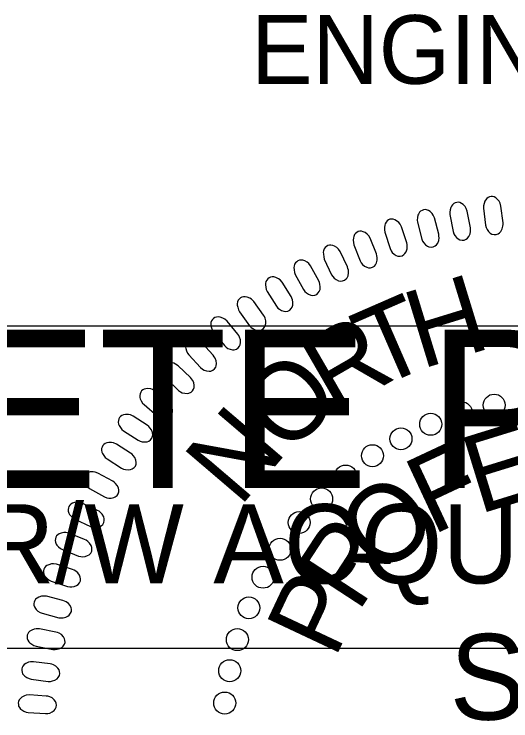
# Model space of a CAD drawing. Extents: x 505602 to 507286, y 483109 to 484209.
# Drawn here: x 507178.9 to 507215, y 484097.2 to 484148.7 of the extents above; entities that cross this region are included whole.
import ezdxf

# ---------------------------------------------------------------- set-up
doc = ezdxf.new("R2010")
doc.units = 0
for name, color, linetype in [('Sheet PE Seal Cell', 7, 'Continuous'), ('Sheet Profile CELL', 7, 'Continuous'), ('Sheet Sticker Incomplete CELL', 7, 'Continuous')]:
    doc.layers.add(name, color=color, linetype=linetype)

msp = doc.modelspace()

# ---------------------------------------------------------------- linework, layer by layer
at = {"layer": 'Sheet PE Seal Cell'}
for points in [[(507214.482, 484133.512), (507214.328, 484134.729), (507214.264, 484134.942), (507214.194, 484135.074), (507214.062, 484135.228), (507213.952, 484135.325), (507213.831, 484135.39), (507213.722, 484135.417), (507213.608, 484135.423), (507213.499, 484135.388), (507213.384, 484135.344), (507213.288, 484135.272), (507213.196, 484135.16), (507213.147, 484135.073), (507213.099, 484134.916), (507213.062, 484134.731), (507213.06, 484134.569), (507213.21, 484133.322), (507213.253, 484133.156), (507213.315, 484133.023), (507213.424, 484132.876), (507213.553, 484132.752), (507213.659, 484132.685), (507213.822, 484132.645), (507213.973, 484132.644), (507214.116, 484132.702), (507214.214, 484132.765), (507214.328, 484132.88), (507214.425, 484133.062), (507214.469, 484133.249), (507214.483, 484133.381)], [(507212.1, 484133.144), (507211.871, 484134.348), (507211.793, 484134.557), (507211.716, 484134.685), (507211.574, 484134.831), (507211.458, 484134.92), (507211.333, 484134.978), (507211.223, 484134.997), (507211.109, 484134.996), (507211.002, 484134.955), (507210.891, 484134.903), (507210.799, 484134.825), (507210.714, 484134.707), (507210.671, 484134.618), (507210.633, 484134.458), (507210.608, 484134.271), (507210.615, 484134.11), (507210.843, 484132.874), (507210.897, 484132.712), (507210.967, 484132.583), (507211.085, 484132.443), (507211.221, 484132.327), (507211.332, 484132.267), (507211.497, 484132.237), (507211.647, 484132.246), (507211.787, 484132.313), (507211.881, 484132.381), (507211.987, 484132.503), (507212.073, 484132.692), (507212.105, 484132.881), (507212.11, 484133.014)], [(507209.795, 484132.672), (507209.491, 484133.86), (507209.4, 484134.063), (507209.314, 484134.186), (507209.164, 484134.322), (507209.042, 484134.404), (507208.914, 484134.453), (507208.802, 484134.467), (507208.689, 484134.458), (507208.585, 484134.411), (507208.477, 484134.352), (507208.39, 484134.268), (507208.314, 484134.145), (507208.276, 484134.053), (507208.247, 484133.891), (507208.234, 484133.703), (507208.252, 484133.543), (507208.557, 484132.324), (507208.621, 484132.165), (507208.699, 484132.041), (507208.826, 484131.909), (507208.969, 484131.801), (507209.083, 484131.749), (507209.25, 484131.729), (507209.4, 484131.747), (507209.535, 484131.822), (507209.624, 484131.897), (507209.722, 484132.025), (507209.795, 484132.219), (507209.816, 484132.41), (507209.813, 484132.542)], [(507207.461, 484132.051), (507207.083, 484133.218), (507206.98, 484133.415), (507206.887, 484133.532), (507206.728, 484133.659), (507206.602, 484133.733), (507206.47, 484133.774), (507206.358, 484133.78), (507206.246, 484133.764), (507206.145, 484133.711), (507206.041, 484133.645), (507205.96, 484133.556), (507205.891, 484133.429), (507205.859, 484133.334), (507205.84, 484133.171), (507205.839, 484132.982), (507205.867, 484132.823), (507206.248, 484131.626), (507206.322, 484131.472), (507206.407, 484131.353), (507206.542, 484131.229), (507206.692, 484131.13), (507206.809, 484131.085), (507206.977, 484131.076), (507207.125, 484131.103), (507207.255, 484131.187), (507207.339, 484131.267), (507207.429, 484131.401), (507207.49, 484131.599), (507207.499, 484131.791), (507207.487, 484131.924)], [(507205.261, 484131.235), (507204.809, 484132.376), (507204.694, 484132.566), (507204.594, 484132.677), (507204.427, 484132.793), (507204.297, 484132.859), (507204.163, 484132.892), (507204.051, 484132.891), (507203.94, 484132.868), (507203.843, 484132.808), (507203.742, 484132.736), (507203.667, 484132.642), (507203.606, 484132.511), (507203.58, 484132.415), (507203.572, 484132.251), (507203.583, 484132.062), (507203.621, 484131.906), (507204.076, 484130.734), (507204.159, 484130.585), (507204.253, 484130.472), (507204.395, 484130.356), (507204.55, 484130.267), (507204.67, 484130.229), (507204.838, 484130.231), (507204.984, 484130.268), (507205.108, 484130.36), (507205.187, 484130.445), (507205.269, 484130.584), (507205.318, 484130.785), (507205.314, 484130.978), (507205.295, 484131.109)], [(507203.143, 484130.302), (507202.621, 484131.412), (507202.494, 484131.594), (507202.387, 484131.699), (507202.214, 484131.805), (507202.079, 484131.862), (507201.944, 484131.887), (507201.832, 484131.879), (507201.722, 484131.849), (507201.629, 484131.783), (507201.534, 484131.705), (507201.464, 484131.607), (507201.412, 484131.472), (507201.392, 484131.374), (507201.395, 484131.21), (507201.417, 484131.022), (507201.464, 484130.868), (507201.993, 484129.729), (507202.085, 484129.584), (507202.185, 484129.477), (507202.334, 484129.371), (507202.495, 484129.292), (507202.617, 484129.261), (507202.784, 484129.274), (507202.928, 484129.319), (507203.046, 484129.419), (507203.12, 484129.509), (507203.192, 484129.653), (507203.229, 484129.857), (507203.213, 484130.048), (507203.185, 484130.179)], [(507201.06, 484129.288), (507200.469, 484130.363), (507200.331, 484130.538), (507200.218, 484130.635), (507200.038, 484130.73), (507199.9, 484130.779), (507199.764, 484130.795), (507199.653, 484130.779), (507199.545, 484130.743), (507199.456, 484130.672), (507199.366, 484130.588), (507199.303, 484130.485), (507199.259, 484130.347), (507199.245, 484130.248), (507199.258, 484130.085), (507199.292, 484129.898), (507199.349, 484129.748), (507199.948, 484128.643), (507200.049, 484128.505), (507200.156, 484128.405), (507200.311, 484128.308), (507200.477, 484128.239), (507200.6, 484128.216), (507200.767, 484128.239), (507200.907, 484128.294), (507201.019, 484128.401), (507201.087, 484128.495), (507201.15, 484128.643), (507201.173, 484128.85), (507201.146, 484129.039), (507201.109, 484129.167)], [(507199.043, 484128.146), (507198.386, 484129.182), (507198.237, 484129.348), (507198.118, 484129.437), (507197.933, 484129.521), (507197.792, 484129.561), (507197.655, 484129.568), (507197.544, 484129.546), (507197.439, 484129.503), (507197.355, 484129.426), (507197.27, 484129.337), (507197.214, 484129.23), (507197.179, 484129.09), (507197.171, 484128.99), (507197.194, 484128.828), (507197.24, 484128.644), (507197.306, 484128.497), (507197.973, 484127.432), (507198.083, 484127.301), (507198.196, 484127.207), (507198.357, 484127.121), (507198.526, 484127.063), (507198.651, 484127.047), (507198.816, 484127.081), (507198.952, 484127.144), (507199.058, 484127.258), (507199.119, 484127.356), (507199.173, 484127.508), (507199.183, 484127.716), (507199.144, 484127.903), (507199.1, 484128.028)], [(507197.042, 484126.791), (507196.321, 484127.784), (507196.162, 484127.94), (507196.038, 484128.022), (507195.847, 484128.094), (507195.704, 484128.125), (507195.567, 484128.124), (507195.458, 484128.095), (507195.356, 484128.045), (507195.277, 484127.963), (507195.198, 484127.869), (507195.149, 484127.759), (507195.122, 484127.616), (507195.121, 484127.517), (507195.155, 484127.356), (507195.211, 484127.175), (507195.287, 484127.033), (507196.019, 484126.012), (507196.137, 484125.888), (507196.255, 484125.801), (507196.421, 484125.724), (507196.594, 484125.678), (507196.72, 484125.67), (507196.882, 484125.714), (507197.015, 484125.786), (507197.112, 484125.906), (507197.167, 484126.007), (507197.212, 484126.163), (507197.209, 484126.371), (507197.158, 484126.555), (507197.106, 484126.678)], [(507195.162, 484125.402), (507194.38, 484126.348), (507194.212, 484126.493), (507194.082, 484126.568), (507193.888, 484126.627), (507193.743, 484126.65), (507193.606, 484126.64), (507193.5, 484126.603), (507193.401, 484126.547), (507193.327, 484126.46), (507193.254, 484126.361), (507193.211, 484126.249), (507193.194, 484126.104), (507193.199, 484126.005), (507193.242, 484125.847), (507193.31, 484125.67), (507193.395, 484125.533), (507194.189, 484124.56), (507194.315, 484124.444), (507194.439, 484124.365), (507194.609, 484124.299), (507194.785, 484124.263), (507194.911, 484124.263), (507195.07, 484124.317), (507195.198, 484124.397), (507195.287, 484124.523), (507195.336, 484124.628), (507195.371, 484124.786), (507195.354, 484124.992), (507195.292, 484125.174), (507195.232, 484125.293)], [(507193.374, 484123.863), (507192.535, 484124.758), (507192.357, 484124.893), (507192.223, 484124.959), (507192.025, 484125.006), (507191.88, 484125.019), (507191.744, 484125.001), (507191.64, 484124.958), (507191.544, 484124.896), (507191.476, 484124.804), (507191.409, 484124.7), (507191.374, 484124.586), (507191.366, 484124.441), (507191.377, 484124.342), (507191.43, 484124.187), (507191.51, 484124.015), (507191.602, 484123.884), (507192.457, 484122.962), (507192.589, 484122.854), (507192.717, 484122.783), (507192.892, 484122.728), (507193.07, 484122.702), (507193.195, 484122.71), (507193.35, 484122.774), (507193.473, 484122.863), (507193.554, 484122.994), (507193.597, 484123.102), (507193.622, 484123.261), (507193.593, 484123.466), (507193.518, 484123.644), (507193.452, 484123.759)], [(507191.712, 484122.254), (507190.818, 484123.094), (507190.632, 484123.217), (507190.495, 484123.275), (507190.294, 484123.309), (507190.148, 484123.314), (507190.013, 484123.286), (507189.912, 484123.237), (507189.821, 484123.169), (507189.759, 484123.074), (507189.699, 484122.966), (507189.67, 484122.849), (507189.671, 484122.705), (507189.689, 484122.606), (507189.751, 484122.454), (507189.841, 484122.288), (507189.942, 484122.162), (507190.853, 484121.297), (507190.992, 484121.197), (507191.124, 484121.134), (507191.302, 484121.09), (507191.48, 484121.076), (507191.605, 484121.092), (507191.757, 484121.166), (507191.873, 484121.261), (507191.946, 484121.397), (507191.982, 484121.508), (507191.996, 484121.669), (507191.955, 484121.872), (507191.87, 484122.044), (507191.796, 484122.154)], [(507190.098, 484120.467), (507189.154, 484121.25), (507188.96, 484121.36), (507188.82, 484121.409), (507188.617, 484121.431), (507188.471, 484121.426), (507188.339, 484121.391), (507188.241, 484121.336), (507188.154, 484121.262), (507188.098, 484121.163), (507188.045, 484121.051), (507188.024, 484120.933), (507188.034, 484120.789), (507188.057, 484120.692), (507188.13, 484120.545), (507188.23, 484120.383), (507188.338, 484120.265), (507189.301, 484119.458), (507189.446, 484119.367), (507189.583, 484119.313), (507189.763, 484119.28), (507189.941, 484119.277), (507190.065, 484119.302), (507190.211, 484119.384), (507190.322, 484119.486), (507190.387, 484119.627), (507190.415, 484119.739), (507190.419, 484119.901), (507190.365, 484120.101), (507190.27, 484120.267), (507190.188, 484120.373)], [(507188.574, 484118.765), (507187.544, 484119.431), (507187.339, 484119.518), (507187.193, 484119.55), (507186.99, 484119.548), (507186.845, 484119.526), (507186.718, 484119.475), (507186.628, 484119.409), (507186.55, 484119.325), (507186.505, 484119.221), (507186.466, 484119.104), (507186.459, 484118.984), (507186.486, 484118.842), (507186.52, 484118.748), (507186.61, 484118.61), (507186.728, 484118.462), (507186.85, 484118.357), (507187.901, 484117.669), (507188.056, 484117.596), (507188.197, 484117.558), (507188.38, 484117.546), (507188.558, 484117.565), (507188.678, 484117.604), (507188.813, 484117.703), (507188.911, 484117.817), (507188.959, 484117.965), (507188.974, 484118.079), (507188.959, 484118.24), (507188.882, 484118.432), (507188.767, 484118.587), (507188.674, 484118.682)], [(507187.359, 484116.742), (507186.324, 484117.4), (507186.119, 484117.486), (507185.973, 484117.517), (507185.769, 484117.513), (507185.625, 484117.49), (507185.497, 484117.438), (507185.408, 484117.371), (507185.33, 484117.287), (507185.287, 484117.181), (507185.249, 484117.065), (507185.243, 484116.944), (507185.271, 484116.802), (507185.306, 484116.709), (507185.397, 484116.572), (507185.516, 484116.425), (507185.639, 484116.321), (507186.696, 484115.641), (507186.851, 484115.569), (507186.993, 484115.532), (507187.175, 484115.522), (507187.353, 484115.542), (507187.473, 484115.581), (507187.607, 484115.682), (507187.704, 484115.797), (507187.751, 484115.944), (507187.765, 484116.06), (507187.749, 484116.221), (507187.67, 484116.412), (507187.554, 484116.565), (507187.461, 484116.66)], [(507186.056, 484114.693), (507184.981, 484115.285), (507184.771, 484115.357), (507184.623, 484115.379), (507184.421, 484115.363), (507184.277, 484115.33), (507184.154, 484115.271), (507184.069, 484115.198), (507183.997, 484115.11), (507183.961, 484115.001), (507183.929, 484114.882), (507183.931, 484114.762), (507183.968, 484114.622), (507184.009, 484114.531), (507184.107, 484114.4), (507184.236, 484114.261), (507184.365, 484114.164), (507185.462, 484113.552), (507185.621, 484113.49), (507185.765, 484113.463), (507185.949, 484113.464), (507186.125, 484113.495), (507186.242, 484113.542), (507186.37, 484113.65), (507186.459, 484113.772), (507186.496, 484113.922), (507186.503, 484114.037), (507186.477, 484114.197), (507186.386, 484114.383), (507186.262, 484114.529), (507186.162, 484114.618)], [(507184.947, 484112.569), (507183.837, 484113.092), (507183.623, 484113.152), (507183.474, 484113.164), (507183.273, 484113.135), (507183.132, 484113.094), (507183.013, 484113.026), (507182.932, 484112.948), (507182.866, 484112.855), (507182.836, 484112.745), (507182.813, 484112.624), (507182.822, 484112.505), (507182.868, 484112.367), (507182.914, 484112.279), (507183.021, 484112.155), (507183.158, 484112.024), (507183.292, 484111.935), (507184.427, 484111.393), (507184.589, 484111.342), (507184.735, 484111.323), (507184.917, 484111.336), (507185.091, 484111.378), (507185.205, 484111.431), (507185.326, 484111.548), (507185.408, 484111.675), (507185.435, 484111.827), (507185.435, 484111.943), (507185.399, 484112.101), (507185.297, 484112.281), (507185.163, 484112.418), (507185.058, 484112.501)], [(507184.008, 484110.451), (507182.868, 484110.902), (507182.65, 484110.948), (507182.501, 484110.952), (507182.302, 484110.91), (507182.164, 484110.86), (507182.049, 484110.785), (507181.973, 484110.702), (507181.913, 484110.605), (507181.89, 484110.494), (507181.874, 484110.371), (507181.891, 484110.252), (507181.945, 484110.118), (507181.997, 484110.033), (507182.112, 484109.915), (507182.257, 484109.794), (507182.396, 484109.714), (507183.562, 484109.244), (507183.727, 484109.203), (507183.874, 484109.193), (507184.055, 484109.217), (507184.226, 484109.27), (507184.337, 484109.331), (507184.451, 484109.455), (507184.524, 484109.586), (507184.542, 484109.74), (507184.534, 484109.856), (507184.488, 484110.011), (507184.374, 484110.184), (507184.232, 484110.313), (507184.122, 484110.389)], [(507183.132, 484108.261), (507181.965, 484108.64), (507181.745, 484108.672), (507181.596, 484108.667), (507181.4, 484108.613), (507181.265, 484108.554), (507181.155, 484108.472), (507181.085, 484108.385), (507181.032, 484108.284), (507181.016, 484108.171), (507181.007, 484108.048), (507181.032, 484107.931), (507181.094, 484107.8), (507181.152, 484107.718), (507181.273, 484107.608), (507181.425, 484107.496), (507181.57, 484107.425), (507182.763, 484107.029), (507182.931, 484106.998), (507183.078, 484106.998), (507183.257, 484107.034), (507183.424, 484107.097), (507183.531, 484107.165), (507183.636, 484107.295), (507183.701, 484107.431), (507183.709, 484107.586), (507183.694, 484107.701), (507183.639, 484107.853), (507183.515, 484108.019), (507183.364, 484108.138), (507183.25, 484108.207)], [(507182.428, 484106.006), (507181.239, 484106.311), (507181.018, 484106.329), (507180.869, 484106.314), (507180.677, 484106.247), (507180.547, 484106.181), (507180.441, 484106.092), (507180.377, 484106), (507180.329, 484105.896), (507180.321, 484105.784), (507180.32, 484105.66), (507180.352, 484105.543), (507180.423, 484105.418), (507180.485, 484105.34), (507180.613, 484105.237), (507180.772, 484105.135), (507180.921, 484105.073), (507182.136, 484104.753), (507182.306, 484104.732), (507182.452, 484104.741), (507182.629, 484104.789), (507182.792, 484104.862), (507182.894, 484104.936), (507182.991, 484105.074), (507183.047, 484105.213), (507183.046, 484105.368), (507183.024, 484105.482), (507182.959, 484105.63), (507182.825, 484105.788), (507182.667, 484105.898), (507182.549, 484105.959)], [(507181.916, 484103.71), (507180.712, 484103.94), (507180.489, 484103.945), (507180.342, 484103.92), (507180.154, 484103.841), (507180.028, 484103.767), (507179.929, 484103.671), (507179.87, 484103.576), (507179.829, 484103.47), (507179.828, 484103.356), (507179.835, 484103.233), (507179.874, 484103.119), (507179.952, 484102.997), (507180.019, 484102.924), (507180.154, 484102.829), (507180.319, 484102.737), (507180.471, 484102.685), (507181.705, 484102.441), (507181.875, 484102.432), (507182.021, 484102.45), (507182.194, 484102.508), (507182.352, 484102.592), (507182.449, 484102.672), (507182.537, 484102.815), (507182.585, 484102.958), (507182.574, 484103.113), (507182.544, 484103.225), (507182.47, 484103.368), (507182.327, 484103.518), (507182.162, 484103.618), (507182.041, 484103.671)], [(507181.496, 484101.395), (507180.279, 484101.549), (507180.057, 484101.54), (507179.911, 484101.506), (507179.729, 484101.416), (507179.608, 484101.334), (507179.515, 484101.232), (507179.462, 484101.134), (507179.428, 484101.024), (507179.434, 484100.911), (507179.449, 484100.788), (507179.495, 484100.677), (507179.581, 484100.561), (507179.653, 484100.492), (507179.792, 484100.406), (507179.963, 484100.324), (507180.118, 484100.282), (507181.364, 484100.116), (507181.535, 484100.118), (507181.679, 484100.145), (507181.848, 484100.213), (507182.001, 484100.307), (507182.093, 484100.394), (507182.172, 484100.542), (507182.211, 484100.688), (507182.189, 484100.841), (507182.153, 484100.951), (507182.07, 484101.09), (507181.917, 484101.229), (507181.747, 484101.319), (507181.623, 484101.364)], [(507181.21, 484099.052), (507179.985, 484099.129), (507179.764, 484099.106), (507179.621, 484099.062), (507179.445, 484098.961), (507179.329, 484098.871), (507179.242, 484098.764), (507179.196, 484098.662), (507179.169, 484098.552), (507179.182, 484098.439), (507179.205, 484098.317), (507179.257, 484098.209), (507179.35, 484098.098), (507179.426, 484098.034), (507179.571, 484097.957), (507179.746, 484097.886), (507179.904, 484097.853), (507181.158, 484097.766), (507181.329, 484097.778), (507181.471, 484097.814), (507181.636, 484097.894), (507181.782, 484097.997), (507181.868, 484098.089), (507181.937, 484098.242), (507181.967, 484098.39), (507181.936, 484098.541), (507181.893, 484098.649), (507181.802, 484098.782), (507181.64, 484098.912), (507181.465, 484098.991), (507181.338, 484099.028)]]:
    msp.add_lwpolyline(points, close=True, dxfattribs=at)
for centre in [(507213.835, 484120.23), (507211.446, 484119.673), (507209.216, 484118.838), (507207.041, 484117.777), (507204.971, 484116.543), (507203.019, 484115.069), (507201.267, 484113.397), (507199.634, 484111.684), (507198.24, 484109.733), (507197.005, 484107.701), (507195.969, 484105.471), (507195.132, 484103.161), (507194.574, 484100.89), (507194.215, 484098.54)]:
    msp.add_circle(centre, 0.801, dxfattribs=at)
at = {"layer": 'Sheet Sticker Incomplete CELL'}
msp.add_lwpolyline([(507095.597, 484102.505), (507095.597, 484126.005), (507242.597, 484126.005), (507242.597, 484102.505)], close=True, dxfattribs=at)

# ---------------------------------------------------------------- texts
at = {"layer": 'Sheet PE Seal Cell'}
for s, height, rotation, p in [('H', 5.669, 17.0557, (507208.505, 484122.835)), ('T', 5.669, 23.5451, (507205.326, 484121.425)), ('R', 5.669, 30.0345, (507202.105, 484119.506)), ('O', 5.669, 43.0132, (507198.63, 484116.478)), ('N', 5.669, 49.5025, (507195.283, 484112.723)), ('E', 5.669, 17.1686, (507212.701, 484112.266)), ('F', 5.669, 25.1084, (507209.311, 484110.727)), ('O', 5.669, 40.988, (507205.614, 484107.589)), ('R', 5.669, 56.8676, (507203.9, 484105.042)), ('P', 5.669, 64.8074, (507202.214, 484101.68)), ('SEAL', 6.2363, 359.9814, (507210.585, 484097.331))]:
    msp.add_text(s, height=height, rotation=rotation, dxfattribs=at).set_placement(p)
at = {"layer": 'Sheet Profile CELL'}
msp.add_text('ENGINEER', height=5.0001, dxfattribs=at).set_placement((507196.142, 484143.624))
at = {"layer": 'Sheet Sticker Incomplete CELL'}
for s, height, p in [('INCOMPLETE PLANS', 11.52, (507104.547, 484114.205)), ('DO NOT USE FOR R/W ACQUISITION', 5.76, (507107.797, 484107.255))]:
    msp.add_text(s, height=height, dxfattribs=at).set_placement(p)

doc.saveas('drawing.dxf')
